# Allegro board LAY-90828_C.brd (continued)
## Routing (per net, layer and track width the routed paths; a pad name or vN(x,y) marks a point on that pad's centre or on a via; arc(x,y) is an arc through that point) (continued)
P1_7: length 53.4
  TOP w0.102: 59.36,32.33 U1.A2
  TOP w0.127: 59.36,32.33 58.61,33.08 58.61,34.1 56.32,36.39 R22.1 56.7,36.9 56.96,37.15 56.96,42.1 59.01,44.15 v1(59.01,46.18)
  BOTTOM w0.127: v1(59.01,46.18) 59.26,46.43 74.25,46.43 74.88,45.8 90.62,45.8 91.88,47.06 J9.9
P1_7/SAI1_RX_FS: length 24.9
  TOP w0.127: v1(58.24,46.18) 58.24,43.77 56.7,42.23 56.7,38.29 R22.2
  BOTTOM w0.127: J1.13 45.64,47.07 49.86,47.07 50.5,46.43 57.99,46.43 v1(58.24,46.18)
P1_8: length 56.2
  TOP w0.102: 58.86,32.33 U1.A1
  TOP w0.127: v1(87.45,42.5) 87.95,42.99 87.95,50.36 89.22,51.63 J9.12 ; 58.86,32.33 58.23,32.96 57.72,32.96 R54.2 56.96,34.74 55.56,36.14 55.56,38.42 56.2,39.06 56.2,42.48 56.85,43.13 v1(56.85,43.89)
  BOTTOM w0.127: v1(87.45,42.5) 86.95,43 74.22,43 73.46,43.77 65.48,43.77 65.36,43.64 57.48,43.64 57.23,43.89 v1(56.85,43.89)
P1_9: length 57.8
  TOP w0.102: 58.86,31.83 U1.B1
  TOP w0.127: J9.11 88.22,47.96 v1(88.22,42.5) ; 58.86,31.83 57.98,32.71 R53.2 56.96,33.09 56.83,33.21 54.82,33.21 54.69,33.34 54.69,37.93 55.94,39.18 55.94,42.61 56.34,43 v1(56.34,44.4)
  BOTTOM w0.127: v1(56.34,44.4) 57.1,44.4 57.61,43.89 65.23,43.89 65.36,44.02 73.58,44.02 74.35,43.26 87.45,43.26 v1(88.22,42.5)
P1_10/SMARTDMA_PIO6-CAMERA_D6: length 59.6
  TOP w0.102: 58.86,31.44 59.59,30.71 60.48,30.71 U1.C3
  TOP w0.127: v1(86.06,41.99) 85.66,42.39 85.66,50.23 86.8,51.38 J9.14 ; 58.86,31.44 58.1,32.2 54.93,32.2 54.43,32.69 54.43,38.06 55.69,39.31 55.69,43.24 v1(55.83,43.39)
  BOTTOM w0.127: v1(86.06,41.99) 85.55,42.5 73.87,42.5 73.1,43.26 65.74,43.26 65.61,43.13 56.09,43.13 v1(55.83,43.39)
P1_11/SMARTDMA_PIO7-CAMERA_D7: length 58.7
  TOP w0.102: U1.D3 60.18,30.5 59.41,30.5 58.86,31.06
  TOP w0.127: v1(86.69,42.5) 86.8,42.61 J9.13 ; v1(55.58,44.4) 55.32,44.15 55.32,42.75 55.43,42.64 55.43,39.44 54.18,38.18 54.18,32.56 54.8,31.94 57.97,31.94 58.86,31.06
  BOTTOM w0.127: v1(86.69,42.5) 86.44,42.75 74.09,42.75 73.33,43.51 65.61,43.51 65.48,43.39 56.59,43.39 v1(55.58,44.4)
P1_12/SMARTDMA_PIO8: length 40.6
  TOP w0.102: 58.86,30.67 59.25,30.29 59.9,30.29 U1.D2
  TOP w0.127: 58.86,30.67 57.85,31.69 54.67,31.69 53.93,32.44 53.93,38.43 54.94,39.45 v1(54.94,41.29) ; v1(67.33,41.04) 67.26,41.1 67.26,43.13 68.02,43.89 68.02,49.86 69.02,50.86 J9.28
  BOTTOM w0.127: v1(54.94,41.29) 55.13,41.1 56.85,41.1 57.23,40.72 63.71,40.72 63.83,40.85 67.13,40.85 v1(67.33,41.04)
P1_13/SMARTDMA_PIO9: length 39
  TOP w0.102: U1.D1 59.16,30 58.86,30.29
  TOP w0.127: 58.86,30.29 57.72,31.44 54.55,31.44 53.67,32.31 53.67,38.69 54.18,39.19 v1(54.18,41.23) ; J9.27 69.02,44.13 67.9,43 v1(67.9,41.48)
  BOTTOM w0.127: v1(67.9,41.48) 67.9,40.85 67.64,40.59 63.96,40.59 63.83,40.46 57.1,40.46 56.72,40.85 54.56,40.85 v1(54.18,41.23)
P1_14/SMARTDMA_PIO10: length 76.5
  TOP w0.102: U1.D4 60.89,29.7 59.07,29.7 58.86,29.91
  TOP w0.127: v1(54.69,44.91) 54.94,44.66 54.94,42.75 53.42,41.23 53.42,32.18 54.42,31.18 57.59,31.18 58.86,29.91
  BOTTOM w0.127: v1(54.69,44.91) 54.94,45.16 57.1,45.16 57.86,44.4 64.98,44.4 65.1,44.53 73.84,44.53 74.6,43.77 91.9,43.77 92.16,43.5 98.11,43.5 100.92,46.31 100.92,50.5 J9.2
P1_15/SMARTDMA_PIO11: length 74.2
  TOP w0.102: U1.E4 58.9,29.5 58.86,29.53
  TOP w0.127: v1(54.43,44.27) 54.43,42.75 53.16,41.48 53.16,32.06 54.29,30.93 57.47,30.93 58.86,29.53
  BOTTOM w0.127: v1(54.43,44.27) 54.82,44.27 55.45,44.91 56.97,44.91 57.74,44.15 65.1,44.15 65.23,44.27 73.71,44.27 74.47,43.51 91.77,43.51 92.04,43.25 98.37,43.25 102.04,46.93 J9.1
P1_16: length 93
  TOP w0.102: U1.F6 v2(62.19,28.52)
  TOP w0.127: R39.1 v1(64.21,39.7) 63.58,39.07 63.58,33.73 v1(63.96,33.35) ; v1(80.72,31.19) 80.72,32.72 76.15,37.29 76.15,37.92 76.79,38.56 v1(76.79,39.45)
  BOTTOM w0.102: v2(62.19,28.52) 62.19,29.17 62.29,29.28 62.29,30.42 63.05,31.18 63.05,32.33
  BOTTOM w0.127: 63.05,32.33 63.96,33.23 v1(63.96,33.35) ; J9.4 100.91,53.04 102.57,53.04 103.46,52.15 103.46,47.83 96.09,40.46 78.06,40.46 77.04,39.45 v1(76.79,39.45) 76.66,39.32 72.6,39.32 71.83,40.08 64.59,40.08 v1(64.21,39.7) ; v1(80.72,31.19) 80.72,30.43 83.6,27.56 83.6,20.06 84.14,19.53 J6.3
P1_16/FC5_I2C_SDA-ARD_D18: length 58.7
  TOP w0.127: v1(63.32,45.16) 63.32,45.04 64.21,44.15 R39.2 ; J2.18 16.73,51.63 17.86,50.5 17.86,48.21 18.49,47.58 19.89,47.58 21.67,45.8 23.83,45.8 24.46,45.16 R6.2 26.62,45.8 28.91,45.8 31.57,43.13 40.21,43.13 42.12,45.04 v1(42.12,45.29)
  BOTTOM w0.127: v1(63.32,45.16) 62.94,45.16 62.69,44.91 58.12,44.91 57.36,45.67 54.05,45.67 53.16,44.78 50.5,44.78 49.23,46.05 43.26,46.05 42.5,45.29 v1(42.12,45.29)
P1_17: length 122.7
  TOP w0.102: U1.F4 60.91,29.28 58.86,29.28
  TOP w0.127: 58.86,29.28 58.74,29.28 57.34,30.67 54.16,30.67 52.91,31.93 v1(52.91,43.51) 53.42,43.51 53.67,43.77 ; v1(97.36,44.27) 97.36,43.13 101.3,39.19 102.69,39.19 106.89,35 106.89,13.54 101.3,7.95 101.3,6.81 100.65,6.16 J7.1
  BOTTOM w0.127: v1(52.91,43.51) 52.91,44.15 54.18,45.42 57.23,45.42 57.99,44.66 64.85,44.66 64.98,44.78 73.97,44.78 74.73,44.02 92.03,44.02 92.28,43.77 96.85,43.77 v1(97.36,44.27) 97.49,44.15 98.25,44.15 99.5,45.4 J9.3
P1_17/FC5_I2C_SCL-ARD_D19: length 48.1
  TOP w0.127: v1(53.04,45.29) 53.16,45.29 R40.2 ; v1(42.5,46.05) 42.75,45.8 42.75,45.16 40.34,42.75 31.45,42.75 29.8,44.4 26.62,44.4 R7.2 25.1,43.77 23.45,45.42 21.54,45.42 19.76,47.2 16.33,47.2 15.19,48.34 15.19,50.62 14.19,51.63 J2.20
  BOTTOM w0.127: v1(53.04,45.29) 52.91,45.16 50.5,45.16 49.35,46.31 42.75,46.31 v1(42.5,46.05)
P1_18/SMARTDMA_PIO14-CAMERA_PDOWN: length 69.8
  TOP w0.102: U1.G4 v2(61.19,28.01)
  TOP w0.127: v1(61.04,51.77) 60.66,51.39 60.66,48.34 59.64,47.32 58.63,47.32 57.36,46.05 57.36,43.26 56.45,42.35 56.45,38.93 55.82,38.29 55.82,36.39 57.85,34.36 v1(57.85,33.61)
  BOTTOM w0.102: 58.86,28.91 61.01,28.91 61.19,28.73 v2(61.19,28.01)
  BOTTOM w0.127: v1(57.85,33.61) 56.85,32.61 56.85,29.29 57.23,28.91 58.86,28.91 ; v1(61.04,51.77) 61.29,52.02 62.05,52.02 63.71,53.67 94.92,53.67 J9.6
P1_19/SMARTDMA_PIO15-CAMERA_RST: length 53.1
  TOP w0.102: U1.G5 v2(61.69,29.02)
  TOP w0.127: v1(64.47,45.16) 64.47,45.04 64.98,44.53 64.98,39.19 64.21,38.43 64.21,34.31 v1(64.02,34.12)
  BOTTOM w0.102: 62.8,32.33 62.8,31.31 62.04,30.55 62.04,29.38 v2(61.69,29.02)
  BOTTOM w0.127: 62.8,32.33 62.8,32.83 64.02,34.06 v1(64.02,34.12) ; v1(64.47,45.16) 64.59,45.04 74.09,45.04 74.85,44.27 91.65,44.27 93.3,45.93 93.8,45.93 J9.5
P1_30/XTAL48M: length 7.3
  TOP w0.102: 58.97,29.01 59.68,29.01 U1.F1
  TOP w0.127: Y3.1 53.26,29.3 53.4,29.15 54.8,29.15 55.06,29.41 C96.1 56.06,29.41 56.2,29.27 R170.1 56.73,29.25 57.12,29.25 57.36,29.01 58.97,29.01
P1_31/EXTAL48M: length 6.2
  TOP w0.102: 58.86,28.75 58.97,28.75 58.99,28.73 59.2,28.73 59.2,28.73 59.92,28.73 U1.F2
  TOP w0.127: 58.86,28.75 57.45,28.75 57.2,28.5 56.73,28.5 R170.2 56.19,28.52 56.08,28.64 C97.1 55.05,28.64 54.89,28.48 Y3.3
P2_0: length 43.8
  TOP w0.102: 58.86,28.2 58.93,28.27 59.92,28.27 U1.H2
  TOP w0.127: J1.6 52.76,52.66 47.96,52.66 47.32,52.02 47.32,46.69 47.83,46.18 47.83,34.11 v1(47.2,33.48) ; v1(52.15,30.09) 51.88,29.82 51.88,28.64 53.15,27.37 56.83,27.37 57.59,28.14 58.8,28.14 58.86,28.2
  BOTTOM w0.127: v1(52.15,30.09) SJ3.1 50.5,30.09 50.37,30.22 50.37,30.94 49.1,32.21 48.47,32.21 v1(47.2,33.48)
P2_1/GPIO: length 46.6
  TOP w0.102: U1.H1 58.98,28 58.86,27.88
  TOP w0.127: 58.86,27.88 58.86,27.88 57.72,27.88 56.96,27.12 53.02,27.12 51.62,28.52 51.62,31.18 52.15,31.71 52.15,39.19 51.64,39.7 51.64,43 51.89,43.26 51.89,45.54 54.05,47.7 54.56,47.7 54.94,48.08 54.94,49.61 55.58,50.24 59.39,50.24 60.4,51.26 60.4,52.66 60.78,53.04 65.08,53.04 J9.30
P2_2/CLKOUT-SMARTDMA_CAMERA_CLKIN: length 71.8
  TOP w0.102: 58.86,27.63 58.99,27.63 59.09,27.73 60.42,27.73 U1.H3
  TOP w0.127: 58.86,27.63 57.85,27.63 57.09,26.86 52.89,26.86 51.37,28.39 51.37,31.31 51.89,31.83 51.89,39.07 51.39,39.58 v1(51.39,44.27) ; J9.16 85.3,50.6 v1(85.3,41.99)
  BOTTOM w0.127: v1(85.3,41.99) 85.04,42.24 73.74,42.24 72.98,43 65.86,43 65.74,42.88 52.78,42.88 v1(51.39,44.27)
P2_3/FXIO_D11: length 99.7
  TOP w0.102: 58.86,27.37 59.12,27.37 59.24,27.5 U1.J3
  TOP w0.127: 58.86,27.37 57.97,27.37 57.21,26.61 54.93,26.61 v1(53.78,25.47)
  BOTTOM w0.127: J8.20 111.57,19.88 113.47,19.88 114.74,18.61 114.74,9.84 113.23,8.33 98.6,8.33 98.1,8.84 94.82,8.84 94.31,8.33 87.71,8.33 86.69,9.35 83.39,9.35 80.47,6.43 64.34,6.43 60.66,10.11 60.66,15.06 59.9,15.83 59.9,18.97 59.61,19.26 58.34,19.26 57.47,20.13 57.47,22.55 55.94,24.07 55.18,24.07 v1(53.78,25.47)
P2_4/FXIO_D12: length 93.5
  TOP w0.102: 58.86,27.12 59.24,27.12 59.4,27.27 60.3,27.27 60.45,27.12 60.57,27.12 U1.K3
  TOP w0.127: 58.86,27.12 58.1,27.12 57.34,26.36 55.31,26.36 54.55,25.59 v1(54.55,25.47)
  BOTTOM w0.127: v1(54.55,25.47) 55.69,24.32 56.07,24.32 57.72,22.67 57.72,20.26 58.47,19.51 59.74,19.51 60.15,19.1 60.15,15.95 60.91,15.19 60.91,10.37 64.59,6.68 80.22,6.68 83.26,9.73 86.82,9.73 87.96,8.59 94.19,8.59 94.69,9.1 98.22,9.1 98.73,8.59 113.1,8.59 114.48,9.97 114.48,17.85 113.73,18.61 J8.21
P2_5/FXIO_D13: length 91.6
  TOP w0.102: U1.K1 59.6,26.91 58.9,26.91 58.86,26.86
  TOP w0.127: 58.86,26.86 58.23,26.86 57.47,26.1 55.82,26.1 55.31,25.59 v1(55.31,25.47)
  BOTTOM w0.127: v1(55.31,25.47) 57.97,22.8 57.97,20.39 58.6,19.76 59.87,19.76 60.4,19.23 60.4,16.08 61.17,15.32 61.17,10.62 64.72,7.06 80.22,7.06 83.26,10.11 86.82,10.11 88.09,8.84 94.06,8.84 94.57,9.35 98.35,9.35 98.86,8.84 112.98,8.84 114.23,10.1 114.23,16.46 113.35,17.34 111.57,17.34 J8.22
P2_6/FXIO_D14: length 85.6
  TOP w0.102: U1.K2 59.89,26.7 59.08,26.7 58.99,26.61 58.86,26.61
  TOP w0.127: v1(56.07,25.47) 56.32,25.21 57.09,25.21 58.48,26.61 58.86,26.61
  BOTTOM w0.127: v1(56.07,25.47) 56.07,25.09 58.23,22.93 58.23,20.51 58.73,20.02 60,20.02 60.66,19.36 60.66,16.21 61.42,15.45 61.42,10.87 64.98,7.32 79.96,7.32 83.14,10.49 86.95,10.49 88.34,9.1 93.93,9.1 94.44,9.6 98.48,9.6 98.98,9.1 112.85,9.1 113.98,10.22 113.98,14.93 J8.23
P2_7: length 68.7
  TOP w0.102: 58.86,26.36 59.12,26.36 59.26,26.5 U1.L2
  TOP w0.127: v1(46.56,34.62) 47.2,35.26 47.2,45.8 44.91,48.08 44.91,50.12 46.16,51.37 J1.12 ; v1(52.28,26.62) 52.28,26.49 52.91,25.86 52.91,25.58 53.53,24.96 57.21,24.96 58.61,26.36 58.86,26.36
  BOTTOM w0.127: J3.13 38.54,7.43 49.09,17.99 52.91,17.99 53.42,18.49 53.42,23.95 52.28,25.1 v1(52.28,26.62) 52.28,26.75 50.12,28.91 50.12,30.81 48.97,31.96 48.08,31.96 46.56,33.48 v1(46.56,34.62)
P2_8/SAI1_TXD0: length 88.8
  TOP w0.102: 58.86,26.1 59.24,26.1 59.41,26.27 59.92,26.27 U1.M2
  TOP w0.127: 58.86,26.1 58.74,26.1 57.34,24.71 53.15,24.71 51.75,26.1 51.75,27.63 51.12,28.26 51.12,31.43 51.64,31.96 51.64,38.94 50.88,39.7 50.88,44.91 53.78,47.81 J1.5 ; R109.1 95.31,35.51 95.31,36.01 95.57,36.26 95.57,44.93 94.69,45.8 91.14,45.8 v1(89.87,47.07)
  BOTTOM w0.127: v1(89.87,47.07) 89.23,47.7 54.79,47.7 53.78,48.71 J1.5
P2_9/SAI1_RXD0: length 98.2
  TOP w0.102: 58.86,25.85 59.37,25.85 59.52,26 U1.M1
  TOP w0.127: R107.1 95.35,32.59 94.82,32.59 93.15,34.26 93.15,39.85 91.26,41.73 v1(91.26,45.04) ; v1(51.26,45.93) 50.62,45.29 50.62,39.58 51.39,38.81 51.39,32.08 50.86,31.56 50.86,28.13 51.5,27.5 51.5,25.98 53.02,24.45 57.47,24.45 58.86,25.85
  BOTTOM w0.127: v1(91.26,45.04) 91.01,45.29 74.63,45.29 73.99,45.93 61.55,45.93 61.04,45.42 58.37,45.42 57.61,46.18 51.51,46.18 v1(51.26,45.93) 50.5,45.93 49.61,46.81 43.36,46.81 J1.15
P2_10/SMARTDMA_PIO31: length 59.6
  TOP w0.102: 58.86,25.47 58.99,25.59 59.5,25.59 59.63,25.72 60.41,25.72 U1.M3
  TOP w0.127: J9.24 74.1,51.25 72.83,49.98 72.83,46.07 73.61,45.29 73.61,41.99 v1(70.44,38.81) ; 58.86,25.47 57.59,24.2 52.89,24.2 51.24,25.85 51.24,27.37 50.61,28.01 50.61,31.69 51.13,32.21 51.13,38.43 v1(50.88,38.69)
  BOTTOM w0.127: v1(70.44,38.81) 70.18,39.07 65.61,39.07 64.59,38.05 53.42,38.05 53.04,38.43 51.13,38.43 v1(50.88,38.69)
P2_11/SMARTDMA_PIO30: length 61
  TOP w0.102: U1.N4 59.78,25.5 59.63,25.34 59.12,25.34 58.86,25.09
  TOP w0.127: 58.86,25.09 57.72,23.94 52.77,23.94 50.99,25.72 50.99,27.25 50.35,27.88 50.35,31.81 50.88,32.34 50.88,37.54 50.24,38.18 50.24,39.19 50.12,39.32 v1(50.12,42.5) ; J9.26 71.56,51.12 70.29,49.85 70.29,44.77 68.4,42.88 68.4,40.72 v1(68.28,40.59)
  BOTTOM w0.127: v1(50.12,42.5) 50.12,42.12 50.75,41.48 53.29,41.48 54.18,40.59 56.59,40.59 56.97,40.21 63.96,40.21 64.09,40.34 68.02,40.34 v1(68.28,40.59)
P3_0/FXIO_D8: length 55.8
  TOP w0.102: 68.52,31.69 67.82,31 U1.B17
  TOP w0.127: v1(71.69,33.34) 71.44,33.09 69.91,33.09 68.52,31.69
  BOTTOM w0.127: v1(71.69,33.34) 71.69,33.6 71.94,33.85 92.52,33.85 94.42,35.75 104.96,35.75 106.36,34.36 106.36,28.26 109.54,25.09 111.44,25.09 J8.17
P3_1/FXIO_D9: length 54.2
  TOP w0.102: 68.52,31.31 67.88,30.67 66.86,30.67 U1.C15
  TOP w0.127: 68.52,31.31 70.04,32.83 71.94,32.83 v1(72.45,33.34)
  BOTTOM w0.127: v1(72.45,33.34) 72.71,33.6 92.65,33.6 94.55,35.5 104.71,35.5 106.11,34.1 106.11,27.88 J8.18
P3_2/FXIO_D10: length 58.6
  TOP w0.102: 68.52,30.93 68.01,30.42 67.12,30.42 66.7,30 U1.D15
  TOP w0.127: v1(70.31,32.21) 69.8,32.21 68.52,30.93
  BOTTOM w0.127: J8.19 111.57,22.42 109.79,22.42 105.85,26.36 105.85,33.98 104.58,35.25 94.68,35.25 92.77,33.34 73.09,33.34 72.45,32.71 70.81,32.71 v1(70.31,32.21)
P3_6/SAI1_MCLK: length 84.8
  TOP w0.102: 68.52,30.55 67.97,30 U1.D17
  TOP w0.127: v1(75.39,47.07) 75.38,47.06 75.38,46.55 74.25,45.42 74.25,34.37 72.45,32.58 72.45,31.94 72.07,31.56 69.53,31.56 68.52,30.55 ; v1(89.11,46.69) 89.11,45.93 90.88,44.15 90.88,41.61 92.9,39.59 92.9,36.89 91.39,35.38 91.39,33.86 93.42,31.83 93.42,30.02 95.31,28.13 R103.2
  BOTTOM w0.127: J1.7 51.24,47.72 51.51,47.45 75.01,47.45 v1(75.39,47.07) 75.64,47.32 88.47,47.32 v1(89.11,46.69)
P3_7/FXIO_D15: length 62.3
  TOP w0.102: 68.52,30.17 68.06,29.71 66.43,29.71 66.19,29.95 U1.D14
  TOP w0.127: 68.52,30.17 69.66,31.31 72.2,31.31 72.96,32.07 v1(72.96,32.33)
  BOTTOM w0.127: J8.24 105.6,20.77 105.6,33.85 104.46,34.99 94.8,34.99 92.9,33.09 73.34,33.09 72.96,32.71 v1(72.96,32.33)
P3_8/FXIO_D16: length 68.2
  TOP w0.102: 68.52,29.79 68.23,29.5 U1.E14
  TOP w0.127: 68.52,29.79 69.79,31.06 72.58,31.06 v1(72.96,31.44)
  BOTTOM w0.127: J8.25 111.57,12.26 109.79,12.26 105.09,16.96 105.09,33.6 104.2,34.48 95.06,34.48 93.15,32.58 74.23,32.58 73.47,31.82 73.34,31.82 v1(72.96,31.44)
P3_9/FXIO_D17: length 64.4
  TOP w0.102: U1.F15 66.98,29.29 68.4,29.29 68.52,29.4
  TOP w0.127: 68.52,29.4 69.91,30.8 72.96,30.8 73.47,31.31 73.47,32.45 v1(73.6,32.58)
  BOTTOM w0.127: J8.26 105.35,18.48 105.35,33.72 104.33,34.74 94.93,34.74 93.03,32.83 73.85,32.83 v1(73.6,32.58)
P3_10/FXIO_D18: length 68.9
  TOP w0.102: 68.52,29.02 67.71,29.02 U1.F17
  TOP w0.127: 68.52,29.02 68.54,29.02 70.06,30.55 73.09,30.55 74.36,31.82 v1(74.48,31.82)
  BOTTOM w0.102: 101.09,33.34 98.11,33.34 97.66,33.79
  BOTTOM w0.127: 101.09,33.34 101.54,33.34 102.17,33.98 103.82,33.98 104.58,33.21 104.58,14.93 109.66,9.85 111.7,9.85 J8.27 ; 97.66,33.79 97.47,33.98 95.31,33.98 93.41,32.07 74.74,32.07 v1(74.48,31.82)
P3_11/FXIO_D19: length 66.3
  TOP w0.102: 68.52,28.75 67.86,28.75 67.81,28.7 67.49,28.7 U1.F16
  TOP w0.127: 68.52,28.75 68.63,28.75 68.64,28.77 68.64,28.77 70.17,30.29 73.47,30.29 v1(73.72,30.55)
  BOTTOM w0.102: 97.66,34.17 98.23,33.6 101.09,33.6
  BOTTOM w0.127: 101.09,33.6 101.41,33.6 102.04,34.23 104.08,34.23 104.84,33.47 104.84,16.45 J8.28 ; v1(73.72,30.55) 73.72,31.69 74.36,32.33 93.28,32.33 95.19,34.23 97.6,34.23 97.66,34.17
P3_12: length 10.8
  TOP w0.102: 68.52,28.5 U1.G16
  TOP w0.127: 68.52,28.5 68.75,28.5 70.29,30.04 73.85,30.04 74.36,30.55 v1(74.36,31.06) 74.87,31.56 R35.1 R37.1
P3_12/FC6_QSPI_D3: length 19.4
  TOP w0.127: R186.2 92.38,25.08 92.15,24.85 U12.7 87.97,24.83 83.14,29.67 81.61,29.67 80.98,30.3 80.47,30.3 v1(80.22,30.56) ; R35.2 76.42,31.56 v1(77.17,30.81)
  BOTTOM w0.127: v1(80.22,30.56) 77.42,30.56 v1(77.17,30.81)
P3_12/PWM1_A0: length 107.1
  TOP w0.127: v1(77.29,31.57) 77.29,31.67 R37.2 76.39,34.13 74.5,36.02 74.5,45.29 76.03,46.81 v1(76.15,46.81) ; v1(49.47,7.69) 49.72,7.94 56.7,7.94 63.18,14.42 63.18,15.43 64.84,17.09 71.69,17.09 72.2,16.58 76.39,16.58 78.93,19.12 78.93,19.5 v1(79.95,20.51)
  BOTTOM w0.127: v1(79.95,20.51) 79.95,25.75 76.53,29.16 76.53,31.07 77.04,31.57 v1(77.29,31.57) ; v1(49.47,7.69) 48.83,7.05 42.23,7.05 J3.15 ; J1.8 51.24,51.62 49.99,50.37 49.99,48.34 51.13,47.2 74.63,47.2 75.26,46.56 75.9,46.56 v1(76.15,46.81)
P3_13: length 9.3
  TOP w0.102: 68.52,28.25 68.28,28.25 68.23,28.29 67.48,28.29 U1.H16
  TOP w0.127: 68.52,28.25 68.88,28.25 69.53,28.9 70.55,28.9 71.31,29.66 74.1,29.66 v1(74.36,29.91) 74.99,30.55 R36.1
P3_13/FC6_QSPI_D2: length 16.8
  TOP w0.127: U12.3 81.49,23.58 R188.2 v1(81.47,24.32) ; R36.2 76.54,30.55 v1(77.04,30.05)
  BOTTOM w0.127: v1(81.47,24.32) 81.47,24.96 80.89,25.54 80.89,25.71 81.16,25.98 81.16,26.16 80.98,26.34 80.8,26.34 80.53,26.07 80.35,26.07 80.18,26.25 80.18,26.43 80.5,26.76 80.5,26.94 80.32,27.12 80.14,27.12 79.82,26.79 79.64,26.79 79.46,26.97 79.46,27.15 79.79,27.48 79.79,27.66 79.61,27.84 79.43,27.84 79.1,27.51 78.92,27.51 78.74,27.69 78.74,27.87 79.13,28.26 79.13,28.44 78.95,28.62 78.77,28.62 78.38,28.23 78.2,28.23 78.02,28.41 78.02,28.59 78.28,28.85 78.28,29.03 78.11,29.21 77.93,29.21 77.66,28.95 77.48,28.95 77.17,29.26 77.17,29.92 v1(77.04,30.05)
P3_14: length 155.8
  TOP w0.102: U1.H17 67.7,27.99 68.52,27.99
  TOP w0.127: J2.4 37.16,54.31 81.1,54.31 83.14,52.28 83.14,42.62 83.9,41.86 v1(83.9,41.48) ; v1(75.01,40.21) 74.75,39.96 74.75,36.27 77.8,33.23 77.8,30.05 77.29,29.54 76.66,29.54 76.28,29.92 75.52,29.92 v1(75.26,29.67) 75,29.67 74.74,29.4 71.44,29.4 70.67,28.64 69.66,28.64 69.02,28.01 69,28.01 68.99,27.99 68.52,27.99 ; v1(47.69,7.94) 48.2,8.45 56.32,8.45 62.67,14.8 62.67,15.68 64.58,17.59 71.94,17.59 72.45,17.09 76.14,17.09 77.66,18.61 v1(77.66,19.75)
  BOTTOM w0.127: v1(77.66,19.75) 77.04,20.37 77.04,27.38 75.26,29.16 v1(75.26,29.67) ; v1(47.69,7.94) 47.31,7.56 40.7,7.56 39.83,6.69 39.83,5.14 39.34,4.65 37.26,4.65 J3.11 ; v1(75.01,40.21) 76.02,40.21 76.53,40.72 83.14,40.72 v1(83.9,41.48)
P3_15: length 106.5
  TOP w0.102: 68.52,27.71 66.98,27.71 U1.H15
  TOP w0.127: 68.52,27.71 69.1,27.71 69.79,28.39 70.8,28.39 71.56,29.15 75.76,29.15 v1(76.02,29.42) 76.28,29.16 77.29,29.16 78.06,29.92 78.06,33.61 75.01,36.65 75.01,39.07 75.52,39.58 75.52,40.72 v1(75.26,40.97) ; v1(78.42,19.75) 78.42,18.99 76.26,16.83 72.33,16.83 71.82,17.34 64.71,17.34 62.93,15.56 62.93,14.67 56.45,8.2 48.96,8.2 v1(48.58,7.81)
  BOTTOM w0.127: SJ1.3 61.42,41.86 61.55,41.99 62.56,41.99 62.94,41.61 65.86,41.61 66.5,42.24 68.15,42.24 69.8,40.59 72.09,40.59 72.85,39.83 73.74,39.83 74.88,40.97 v1(75.26,40.97) ; v1(76.02,29.42) 76.02,29.03 77.42,27.64 77.42,23.19 78.18,22.43 78.18,19.99 v1(78.42,19.75) ; J3.9 34.98,4.4 39.44,4.4 40.08,5.04 40.08,6.56 40.83,7.31 48.07,7.31 v1(48.58,7.81)
P3_16: length 150.9
  TOP w0.102: U1.J15 68.01,27.5 68.05,27.45 68.52,27.45
  TOP w0.127: 68.52,27.45 69.23,27.45 69.91,28.13 70.93,28.13 71.69,28.9 77.41,28.9 78.31,29.8 78.31,34.11 75.64,36.78 75.64,38.18 76.02,38.56 76.02,44.66 77.04,45.67 77.04,47.45 v1(77.8,48.21) ; R106.1 95.82,35.89 95.82,45.05 94.57,46.31 91.39,46.31 v1(90.76,46.94) ; v1(52.91,31.19) 52.66,31.45 52.66,39.58 52.49,39.74 52.49,39.96 v1(52.43,40.02) 52.43,45.32 54.31,47.2 57.86,47.2 58.86,48.2 J1.1
  BOTTOM w0.127: J1.1 60,47.96 77.55,47.96 v1(77.8,48.21) 78.06,47.96 89.74,47.96 v1(90.76,46.94) ; J3.7 32.08,7.06 36.53,7.06 37.29,6.3 37.29,5.29 37.67,4.9 39.07,4.9 39.58,5.41 39.58,7.95 49.35,17.73 53.04,17.73 53.67,18.37 53.67,24.21 52.91,24.97 v1(52.91,31.19) ; v1(52.43,40.02) 53.51,38.94 SJ2.3
P3_17: length 160.2
  TOP w0.102: 68.52,27.2 67.93,27.2 67.83,27.29 66.98,27.29 U1.K15
  TOP w0.127: v1(78.95,31.45) 78.95,30.05 77.54,28.64 71.82,28.64 71.06,27.88 70.04,27.88 69.4,27.25 69.38,27.25 69.34,27.2 68.52,27.2 ; J1.11 46.16,47.31 47.45,46.03 47.45,34.5 v1(47.2,34.24) 46.43,33.48 46.43,31.96 45.53,31.06 45.53,24.32 43.5,22.29 43.5,19.75 v1(42.99,19.24) ; R108.1 95.9,33.93 v1(95.06,33.09) 94.8,33.34 94.8,35.88 95.31,36.39 95.31,44.8 94.57,45.54 90.5,45.54 89.87,46.18 v1(89.87,46.31)
  BOTTOM w0.127: v1(89.87,46.31) 89.61,46.05 75.01,46.05 74.37,46.69 50.62,46.69 49.99,47.32 46.94,47.32 46.16,48.1 J1.11 J1.14 ; J3.5 31.05,8.58 31.05,13.15 36.26,18.36 37.4,18.36 38.29,19.24 v1(42.99,19.24) ; v1(95.06,33.09) 93.67,31.7 79.2,31.7 v1(78.95,31.45) ; v1(47.2,34.24) 47.45,34.24 49.23,32.46 50.59,32.46 SJ3.3
P3_18/SAI1_RX_BCLK: length 62.5
  TOP w0.102: U1.K16 67.48,26.71 67.98,26.71 68.13,26.86 68.52,26.86
  TOP w0.127: 68.52,26.86 69.87,26.86 69.87,26.86 70.42,26.86 71.94,28.39 77.66,28.39 79.45,30.18 79.45,33.48 75.9,37.04 75.9,38.05 76.28,38.43 76.28,44.4 77.55,45.67 v1(77.55,46.56)
  BOTTOM w0.127: v1(77.55,46.56) 77.29,46.31 75.14,46.31 74.5,46.94 50.85,46.94 J1.9
P3_20: length 15.3
  TOP w0.102: U1.M17 67.78,26.09 68.41,26.09 68.42,26.1 68.52,26.1
  TOP w0.127: 68.52,26.1 70.19,26.1 70.19,26.1 70.8,26.1 72.33,27.63 77.69,27.63 78.18,27.13 80.46,27.13 v1(80.96,27.63) 81.34,27.63 R32.1
P3_20/FC6_QSPI_D0: length 13.5
  TOP w0.127: R32.2 83.76,28.01 86.04,25.72 86.04,25.04 85.9,24.9 85.9,24.72 86.08,24.54 86.26,24.54 86.53,24.8 86.7,24.8 86.88,24.62 86.88,24.44 86.62,24.18 86.62,24 86.8,23.82 86.98,23.82 87.24,24.09 87.42,24.09 87.6,23.91 87.6,23.73 87.34,23.46 87.34,23.28 87.52,23.1 87.7,23.1 87.9,23.3 88.08,23.3 88.26,23.12 88.26,22.74 88.7,22.3 v1(89.09,22.3) 89.46,22.3 U12.5
P3_21: length 18.3
  TOP w0.102: 68.52,26.61 68.24,26.61 68.13,26.5 U1.L16
  TOP w0.127: 68.52,26.61 69.98,26.61 69.98,26.61 70.55,26.61 72.07,28.13 78.17,28.13 79.06,29.02 79.31,29.02 v1(79.44,29.15) 79.44,29.66 79.56,29.79 79.82,29.79 79.95,29.66 79.95,29.15 80.07,29.02 80.33,29.02 80.45,29.15 80.45,29.79 80.58,29.91 80.83,29.91 80.96,29.79 80.96,29.15 81.09,29.02 R33.1
P3_21/FC6_QSPI_SCK: length 10.3
  TOP w0.127: R33.2 83.25,29.02 88.7,23.58 v1(89.08,23.57) U12.6
P3_22: length 12.5
  TOP w0.102: 68.52,26.36 68.28,26.36 68.22,26.3 67.49,26.3 U1.M16
  TOP w0.127: 68.52,26.36 70.08,26.36 70.08,26.36 70.67,26.36 72.2,27.88 R34.1
P3_22/FC6_QSPI_D1: length 15.6
  TOP w0.127: R34.2 v1(80.58,28.52) ; U12.2 82.36,24.83 v1(82.1,24.58)
  BOTTOM w0.127: v1(80.58,28.52) 80.86,28.52 81.88,27.5 83.12,27.5 83.25,27.37 83.25,27.12 83.12,26.99 81.34,26.99 81.22,26.86 81.22,26.61 81.34,26.48 82.99,26.48 83.12,26.36 83.12,26.1 82.99,25.98 81.72,25.98 81.6,25.85 81.6,25.59 81.72,25.47 82.99,25.47 83.12,25.34 83.12,25.09 82.99,24.96 82.23,24.96 82.1,24.83 v1(82.1,24.58)
P3_23: length 13.4
  TOP w0.102: 68.52,25.85 68.01,25.85 67.87,25.71 66.98,25.71 U1.M15
  TOP w0.127: R31.1 78.32,26.61 77.56,27.37 72.45,27.37 70.93,25.85 70.29,25.85 70.29,25.85 68.52,25.85
P3_23/FC6_QSPI_CS0: length 3.8
  TOP w0.127: R31.2 80.96,26.61 R187.2 U12.1
P4_0: length 220.8
  TOP w0.102: U1.P1 59.16,25 58.86,24.71
  TOP w0.127: v1(106.25,37.04) 107.39,35.89 107.39,13.03 102.19,7.83 102.19,4.78 99.14,1.73 91.39,1.73 90.74,2.38 J7.8 ; v1(57.36,52.91) 58.5,54.05 77.8,54.05 79.18,52.67 J9.20 80.34,50.47 80.34,43.64 83.01,40.97 89.71,40.97 J5.6 91.76,38.42 91.01,37.67 89.61,37.67 89.11,37.16 89.11,35.75 v1(89.85,35) R49.1 ; 58.86,24.71 57.85,23.69 52.64,23.69 50.74,25.59 50.74,27.12 50.1,27.75 50.1,28.77 R44.2 49.21,30.03 v1(49.55,30.37) 49.55,30.5 49.35,30.69 49.35,31.57 50.62,32.84 50.62,37.42 49.99,38.05 49.99,39.07 49.61,39.45 49.61,45.04 51.89,47.32 52.28,47.32 v1(52.91,47.96) ; v1(30.54,15.05) 29.4,16.2 19.11,16.2 18.86,16.45 R210.2 ; v1(91.96,34.81) 91.96,33.67 94.52,31.11 R105.1
  BOTTOM w0.127: v1(89.85,35) 90.04,34.81 v1(91.96,34.81) 92.34,34.81 94.06,36.53 105.74,36.53 v1(106.25,37.04) 107.52,38.31 107.52,39.83 109.16,41.47 J8.4 ; v1(52.91,47.96) 52.66,48.21 52.66,49.99 53.16,50.5 56.97,50.5 57.48,51.01 57.48,52.78 v1(57.36,52.91) ; v1(49.55,30.37) 49.55,30.5 49.1,30.94 46.17,30.94 45.53,30.29 40.32,30.29 37.78,27.75 37.78,21.02 36.64,19.88 36.13,19.88 31.3,15.05 v1(30.54,15.05)
P4_0/FC2_I2C_SDA-ACCL: length 2.9
  TOP w0.127: R49.2 89.85,32.33 88.98,31.46 U10.4
P4_1: length 220.2
  TOP w0.102: U1.P2 59.77,24.58 59.12,24.58 58.86,24.32
  TOP w0.127: J7.6 93.28,2.51 93.68,2.11 99.01,2.11 101.83,4.93 101.83,7.97 107.14,13.29 107.14,35.38 105.62,36.91 v1(105.62,37.54) ; v1(92.41,35.51) 92.41,34.62 94.9,32.13 R104.1 ; R211.2 18.48,17.34 19.37,16.45 29.91,16.45 v1(30.54,15.82) ; 58.86,24.32 57.97,23.44 52.51,23.44 50.48,25.47 50.48,26.99 49.85,27.63 49.85,28.54 49.62,28.77 R43.2 49.21,28.39 49.08,28.26 47.94,28.26 47.69,28.52 47.69,30.17 48.85,31.33 v1(48.85,31.45) 50.37,32.97 50.37,37.29 49.74,37.92 49.74,38.94 49.35,39.32 49.35,45.29 v1(52.02,47.96) ; R50.1 88.84,34.99 v1(88.85,35) 88.72,35.13 88.72,37.42 89.22,37.91 J5.5 87.43,40.72 82.88,40.72 79.18,44.42 J9.19 79.18,50.13 78.18,51.13 78.18,52.91 77.29,53.8 59.01,53.8 v1(58.12,52.91)
  BOTTOM w0.127: v1(58.12,52.91) 57.61,53.42 53.29,53.42 52.4,52.53 52.4,48.21 52.15,47.96 v1(52.02,47.96) ; v1(48.85,31.45) 46.17,31.45 45.27,30.55 40.19,30.55 37.4,27.75 37.4,21.15 36.51,20.26 34.73,20.26 30.54,16.07 v1(30.54,15.82) ; J8.3 111.57,42.74 109.54,42.74 107.27,40.46 107.27,39.19 v1(105.62,37.54) 104.85,36.78 93.93,36.78 92.66,35.51 v1(92.41,35.51) 89.36,35.51 v1(88.85,35)
P4_1/FC2_I2C_SCL-ACCL: length 1.9
  TOP w0.127: R50.2 88.84,31.99 88.71,31.86 U10.5
P4_2: length 96.1
  TOP w0.102: 58.86,23.94 58.92,24 U1.T1
  TOP w0.127: v1(75.52,38.81) 75.77,39.07 75.77,44.91 76.79,45.93 76.79,47.2 75.64,48.34 75.64,52.53 74.88,53.29 60.66,53.29 60.15,52.78 60.15,51.39 59.26,50.5 57.99,50.5 56.86,51.63 J1.4 54.94,50.24 50.75,50.24 50.12,49.61 50.12,48.34 49.1,47.32 49.1,39.19 49.48,38.81 49.48,37.8 50.12,37.16 50.12,34.24 49.35,33.48 49.35,33.1 48.07,31.81 48.07,31.31 47.18,30.42 47.18,27.88 47.81,27.25 48.96,27.25 49.21,27.5 R55.2 50.23,26.74 50.23,25.34 52.39,23.18 58.11,23.18 58.86,23.94
  BOTTOM w0.127: v1(75.52,38.81) 76.79,38.81 78.18,40.21 85.4,40.21 J5.4
P4_3: length 89
  TOP w0.102: U1.U1 58.86,23.5
  TOP w0.127: 58.86,23.5 58.81,23.5 58.23,22.93 52.26,22.93 49.97,25.21 49.97,25.98 R56.2 49.21,26.36 49.08,26.23 47.56,26.23 46.67,27.12 46.67,30.67 47.56,31.56 47.56,32.07 48.85,33.35 48.85,34.37 49.86,35.38 49.86,37.04 49.23,37.67 49.23,38.69 48.85,39.07 48.85,47.45 49.86,48.47 49.86,49.74 50.62,50.5 54.56,50.5 55.2,51.13 55.2,52.66 55.58,53.04 56.47,53.04 57.87,51.63 J1.2 58.86,51.88 60.53,53.55 76.41,53.55 77.8,52.15 77.8,48.97 78.44,48.34 78.44,44.78 84.14,39.08 J5.3
P4_4/SMARTDMA_PIO28: length 29.5
  TOP w0.102: U1.M6 v2(62.19,26.48)
  TOP w0.127: v1(69.8,36.02) 69.8,38.94 73.1,42.24 73.1,45.16 71.56,46.7 J9.25
  BOTTOM w0.102: 65.98,32.33 64.72,31.07 64.72,29.43 63.05,27.76 63.05,26.85 62.68,26.48 v2(62.19,26.48)
  BOTTOM w0.127: 65.98,32.33 66.75,33.1 68.4,33.1 69.8,34.5 v1(69.8,36.02)
P4_5/SMARTDMA_PIO29: length 29.8
  TOP w0.102: U1.M8 v2(63.19,26.47)
  TOP w0.127: v1(73.48,36.02) 73.99,36.53 73.99,48.98 J9.23
  BOTTOM w0.102: 66.49,32.33 64.98,30.81 64.98,29.29 63.33,27.65 63.33,27.65 63.31,27.62 63.31,26.61 63.19,26.49 v2(63.19,26.47)
  BOTTOM w0.127: v1(73.48,36.02) 73.23,36.27 72.09,36.27 68.66,32.84 67.01,32.84 66.49,32.33
P4_6: length 126.1
  TOP w0.102: U1.N7 v2(62.2,25.5)
  TOP w0.127: J8.6 110.58,38.93 111.84,37.67 114.25,37.67 115.39,36.53 115.39,13.79 113.74,12.14 108.03,12.14 107.01,11.13 v1(106.5,11.13) ; v1(58.24,13.92) 58.37,13.79 59.38,13.79 61.92,16.33 62.56,16.33 64.47,18.24 v1(64.47,18.62)
  BOTTOM w0.102: v2(62.2,25.5) 62.2,25.46 63.58,24.08 63.58,22.67
  BOTTOM w0.127: J4.2 46.16,2.35 46.42,2.1 57.09,2.1 57.59,2.61 57.59,4.39 57.85,4.64 57.85,6.8 57.97,6.93 57.97,13.78 58.12,13.92 v1(58.24,13.92) ; 63.58,22.67 63.58,19.51 v1(64.47,18.62) 65.86,17.22 66.75,17.22 67.64,16.33 73.61,16.33 75.9,14.05 81.74,14.05 83.26,12.52 86.44,12.52 88.6,10.37 93.55,10.37 94.69,11.51 106.12,11.51 v1(106.5,11.13)
P4_7/FXIO_LCD_RST: length 107.8
  TOP w0.102: 58.86,23.07 60.25,23.07 U1.T4
  TOP w0.127: 58.86,23.07 58.75,23.07 58.36,22.67 57.21,22.67 v1(56.96,22.42)
  BOTTOM w0.127: J8.7 115.75,33.48 115.75,9.33 111.33,4.9 82.25,4.9 82,5.15 62.7,5.15 59.24,8.6 59.24,14.45 57.99,15.7 57.99,19.1 57.21,19.88 57.21,22.17 v1(56.96,22.42)
P4_12/ARD_A4: length 36.6
  TOP w0.102: 61.79,22.67 62.48,23.37 62.48,23.71 U1.T6
  TOP w0.127: R299.2 49.21,25.59 52.13,22.67 55.94,22.67 v1(56.2,22.42) 56.69,21.92 57.99,21.92 58.63,22.56 61.67,22.56 61.79,22.67
  BOTTOM w0.127: v1(56.2,22.42) 56.2,21.91 55.69,21.4 55.69,14.16 56.2,13.66 56.2,8.45 57.34,7.31 57.34,5.15 56.32,4.13 J4.10
P4_13: length 36.8
  TOP w0.102: 62.17,22.67 62.69,23.19 U1.T7
  TOP w0.127: R298.2 R57.1 50.48,23.94 52.01,22.42 55.56,22.42 56.07,21.91 56.2,21.91 v1(56.7,21.4) 56.97,21.67 58.12,21.67 58.63,22.18 61.67,22.18 62.17,22.67
  BOTTOM w0.127: J4.12 59.88,4.39 59.88,6.54 58.99,7.43 58.99,14.32 57.74,15.57 57.74,18.85 56.96,19.63 56.96,21.28 56.83,21.4 v1(56.7,21.4)
P4_13/TRIG_IN8-MC_ENC_B: length 35.9
  TOP w0.127: v1(44.77,19.37) 44.51,19.63 44.51,21.78 46.67,23.94 R57.2
  BOTTOM w0.127: v1(44.77,19.37) 44.13,20.01 38.42,20.01 37.02,18.61 36.13,18.61 30.8,13.28 30.8,12.51 28.38,10.1 26.22,10.1 23.3,7.18 J3.1
P4_14/FXIO_LCD_CS: length 83.7
  TOP w0.102: v2(62.72,25.97) 62.8,25.89 62.8,25.89 U1.N8
  TOP w0.127: J8.9 114.36,32.33 114.36,13.28 113.48,12.4 107.52,12.4 v1(106.95,11.83)
  BOTTOM w0.102: 63.83,22.67 63.83,24.85 62.72,25.97 v2(62.72,25.97)
  BOTTOM w0.127: v1(106.95,11.83) 106.88,11.76 94.57,11.76 93.42,10.62 88.72,10.62 86.57,12.78 83.52,12.78 81.99,14.3 76.02,14.3 73.74,16.59 67.77,16.59 66.88,17.48 66.5,17.48 63.83,20.14 63.83,22.67
P4_15: length 34.9
  TOP w0.102: U1.T8 62.89,23.7 62.89,23.01 62.55,22.67
  TOP w0.127: 62.55,22.67 61.04,21.16 57.48,21.16 57.22,20.9 56.32,20.9 R25.1 55.94,21.53 55.56,21.91 v1(55.31,21.91)
  BOTTOM w0.127: J4.4 49.97,4.64 54.16,4.64 54.93,5.4 54.93,8.32 53.66,9.59 53.66,17.21 55.31,18.86 v1(55.31,21.91)
P4_15/CAN1_RXD: length 1.8
  TOP w0.127: U11.4 54.2,21.49 54.42,21.28 R25.2
P4_16: length 59.6
  TOP w0.102: U1.R8 63.48,24.21 63.48,23.22 62.93,22.67
  TOP w0.127: 62.93,22.67 61.17,20.91 60.15,20.91 56.96,17.72 v1(56.2,17.72) R67.1 ; R92.1 37.27,16.06 37.53,16.32 40.19,16.32 40.58,15.94 40.58,15.05 40.19,14.67 40.19,9.72 41.08,8.83 43.37,8.83 44.89,7.31 44.89,4.64 45.15,4.39 50.23,4.39 J4.6
  BOTTOM w0.127: v1(56.2,17.72) 56.2,14.29 56.58,13.91 56.58,8.58 57.59,7.56 57.59,4.77 57.34,4.51 57.34,2.73 56.96,2.35 52.26,2.35 J4.6
P4_16/CAN1_TXD: length 2.4
  TOP w0.127: U11.1 53.74,19.54 54.8,18.48 R67.2
P4_17: length 102.6
  TOP w0.102: 63.31,22.67 63.69,23.05 U1.R9
  TOP w0.127: v1(58.5,18.62) 58.5,18.63 60.52,20.65 61.29,20.65 63.31,22.67 ; R169.2 100.92,7.32 v1(100.66,7.06) ; v1(60.9,7.7) 60.9,2.99 60.13,2.23 54.93,2.23 J4.8 52.51,2.1 45.02,2.1 44.64,2.48 44.64,7.18 43.24,8.58 40.96,8.58 39.94,9.59 39.94,14.42 39.69,14.67 R88.1
  BOTTOM w0.127: v1(58.5,18.62) 58.24,18.37 58.24,15.83 59.5,14.57 59.5,9.1 v1(60.9,7.7) 63.19,5.4 81.09,5.4 82.99,7.31 100.42,7.31 v1(100.66,7.06)
P4_18: length 78.3
  TOP w0.102: v2(63.71,25.86) 64.07,25.5 U1.N10
  TOP w0.127: v1(93.53,11.64) R167.2 ; v1(82.76,31.19) 82.76,32.97 79.06,36.67 J5.1
  BOTTOM w0.102: 67.01,22.67 67.01,23.32 65.86,24.46 65.48,24.46 64.09,25.86 v2(63.71,25.86)
  BOTTOM w0.127: 67.01,22.67 67.01,21.67 65.86,20.53 65.86,18.87 67.77,16.97 73.74,16.97 76.15,14.56 82.12,14.56 83.52,13.16 86.57,13.16 88.85,10.87 92.77,10.87 v1(93.53,11.64) 93.53,14.57 92.92,15.19 92.92,17.1 90.63,19.38 85.8,19.38 84.66,20.53 84.66,28.27 82.76,30.18 v1(82.76,31.19)
P4_19: length 101.2
  TOP w0.102: U1.R10 63.9,24.21 63.9,22.88 63.69,22.67
  TOP w0.127: v1(95.2,8.08) 94.69,8.08 93.79,8.99 R168.2 ; 63.69,22.67 59.77,18.75 v1(59.39,18.75)
  BOTTOM w0.127: v1(59.39,18.75) 59.51,18.62 59.51,17.86 58.88,17.22 58.88,15.95 60.02,14.81 60.02,9.73 63.84,5.91 80.83,5.91 82.74,7.81 94.94,7.81 v1(95.2,8.08) 97.87,8.08 98.13,7.81 113.47,7.81 115.25,9.59 115.25,28.9 J8.11
P4_20/FXIO_LCD_WR: length 104.5
  TOP w0.102: 64.08,22.67 64.48,23.08 64.48,23.71 U1.T10
  TOP w0.127: 64.08,22.67 59.51,18.11 v1(59.01,18.11)
  BOTTOM w0.127: v1(59.01,18.11) 58.5,17.6 58.5,15.95 59.75,14.7 59.75,9.59 63.69,5.66 80.96,5.66 82.87,7.56 113.6,7.56 115.5,9.46 115.5,30.68 113.47,32.71 111.44,32.71 J8.10
P4_21/TRIG_IN9-MC_ENC_A: length 50.1
  TOP w0.102: U1.T11 64.69,22.91 64.46,22.67
  TOP w0.127: v1(52.78,18.62) 53.9,18.62 55.42,17.1 57.99,17.1 58.5,17.6 59.39,17.6 64.46,22.67
  BOTTOM w0.127: J3.3 27.11,4.64 29.29,4.64 29.8,5.15 29.8,6.56 30.69,7.44 38.17,7.44 48.97,18.24 52.4,18.24 v1(52.78,18.62)
P4_22/FXIO_D30-CAMERA_PCLK: length 84.2
  TOP w0.102: 64.84,22.67 64.9,22.73 64.9,23.71 U1.T12
  TOP w0.127: 64.84,22.67 64.84,22.55 59.64,17.35 58.63,17.35 57.61,16.33 44.27,16.33 39.32,21.29 39.32,31.83 40.21,32.72 40.21,37.16 45.16,42.12 45.16,43 45.8,43.64 v1(45.8,45.54)
  BOTTOM w0.127: v1(45.8,45.54) 48.97,45.54 51.89,42.62 65.86,42.62 65.99,42.75 68.66,42.75 69.42,41.99 SJ4.3
P4_23/FXIO_LCD_TE: length 99.2
  TOP w0.102: 65.21,22.67 65.21,23.48 U1.U12
  TOP w0.127: 65.21,22.67 65.21,22.41 59.51,16.72 v1(59.39,16.72)
  BOTTOM w0.127: v1(59.39,16.72) 59.39,15.83 60.28,14.94 60.28,9.98 64.09,6.17 80.72,6.17 82.62,8.07 94.43,8.07 94.95,8.59 97.87,8.59 98.38,8.08 113.36,8.08 114.99,9.72 114.99,28.52 113.47,30.04 111.57,30.04 J8.12
P5-9V_VIN: length 27.2
  TOP w0.762: J19.1 27.36,13.02 26.73,12.39 C112.1 C110.1 C111.1 30.67,11.37 31.18,10.86 31.18,8.58 32.07,7.69 41.97,7.69 42.73,6.93 42.73,4 42.1,3.37 J3.16
P5_0/EXTAL32K: length 5.4
  TOP w0.127: U1.U16 67.19,20.7 67.37,20.51 C95.1 67.75,20.01 67.01,19.27 Y2.2
P5_1/XTAL32K: length 6.4
  TOP w0.127: Y2.1 69.51,19.27 68.64,20.13 C94.1 69.02,20.51 69.15,20.64 69.15,22.17 68.52,22.8 67.88,22.8 67.69,22.99 U1.U17
P5_2/MIKROE_RESET: length 23
  TOP w0.102: v2(64.19,26.49) U1.M10
  BOTTOM w0.102: v2(64.19,26.49) 64.85,26.49 64.98,26.62 68.02,26.62 68.28,26.37 68.52,26.37
  BOTTOM w0.127: J6.2 81.61,16.09 81.61,17.1 79.83,18.87 77.12,18.87 69.63,26.37 68.52,26.37
P5_3/ADC1_B11-MIKROE_AN: length 20.3
  TOP w0.102: v2(64.69,25.99) U1.N11
  BOTTOM w0.102: v2(64.69,25.99) 65.06,26.37 67.9,26.37 68.3,25.96 68.52,25.96
  BOTTOM w0.127: J6.1 79.06,17.88 78.31,18.62 77.02,18.62 69.67,25.96 68.52,25.96
P5_4/PMOD_RESET: length 47.6
  TOP w0.102: U1.M12 v2(65.19,25.48)
  TOP w0.127: v1(91.77,11.64) 92.28,11.13 92.28,8.84 94.57,6.56 94.57,4.88 J7.4
  BOTTOM w0.102: 67.39,22.67 67.39,23.32 66.37,24.34 66.37,25.1 65.99,25.48 v2(65.19,25.48)
  BOTTOM w0.127: v1(91.77,11.64) 91.26,11.13 89.11,11.13 86.82,13.41 83.77,13.41 82.37,14.81 76.28,14.81 73.74,17.35 67.77,17.35 66.25,18.87 66.25,20.53 67.39,21.67 67.39,22.67
P5_5/PMOD_INT: length 50.6
  TOP w0.102: U1.K12 65.19,27.41 65.09,27.51 v2(64.98,27.51)
  TOP w0.127: v1(89.23,11.64) 89.49,11.38 89.49,5.16 89.87,4.78 93.8,4.78 94.57,4.02 94.57,2.87 94.95,2.49 97.23,2.49 J7.2
  BOTTOM w0.102: 68.52,26.62 68.26,26.88 65.61,26.88 v2(64.98,27.51)
  BOTTOM w0.127: v1(89.23,11.64) 87.07,13.79 84.03,13.79 82.76,15.06 82.76,17.48 80.99,19.24 77.28,19.24 69.9,26.62 68.52,26.62
P5_6/MIKROE_INT: length 24.9
  TOP w0.102: v2(65.69,27.51) U1.K13
  TOP w0.127: J5.2 81.6,35.51 v1(81.87,35.24)
  BOTTOM w0.102: v2(65.69,27.51) 65.69,28.1 67.39,29.8 67.39,31.32 67.77,31.7 68.52,31.7
  BOTTOM w0.127: 68.52,31.7 69.17,31.7 71.71,34.24 73.99,34.24 74.99,35.24 v1(81.87,35.24)
P5_7: length 87.5
  TOP w0.102: v2(65.69,25.99) U1.L13
  TOP w0.127: v1(21.65,1.97) 21.14,2.48 21.14,14.67 20.89,14.93 17.09,14.93 16.96,15.05 R257.2 16.45,15.43 15.81,14.8 15.3,14.8 15.14,14.96 U41.6 ; v1(66.74,20.39) 66.12,20.39 64.98,19.24 64.98,18.37 62.69,16.08 62.05,16.08 59,13.03 v1(58.5,13.03)
  BOTTOM w0.102: 67.77,22.67 67.77,23.32 66.63,24.46 66.63,25.35 65.99,25.99 v2(65.69,25.99)
  BOTTOM w0.127: v1(21.65,1.97) 21.78,1.85 57.21,1.85 57.85,2.48 57.85,4.26 58.86,5.27 J4.11 58.23,6.54 58.23,12.76 v1(58.5,13.03) ; v1(66.74,20.39) 66.86,20.39 67.77,21.29 67.77,22.67
PIO0_5-ISP_EN-LED_SWD_ACT: length 17.8
  TOP w0.127: D7.C 27.46,38.14 28,38.68 JP5.2 R127.2 ; U8.A7 28.51,27.88 v2(28.76,28.13)
  BOTTOM w0.102: 28.76,31.82 v2(28.76,28.13)
  BOTTOM w0.127: JP5.2 29.53,37.27 28.51,36.26 28.51,32.2 28.76,31.94 28.76,31.82
SNS_LIGHT_ADC: length 28.5
  TOP w0.127: v1(61.67,39.45) 61.67,38.57 R38.1 ; Q2.2 37.79,44.78 C100.1 R178.1 v1(40.85,44.78)
  BOTTOM w0.127: v1(61.67,39.45) 61.17,39.96 56.85,39.96 56.47,40.34 54.05,40.34 53.16,41.23 50.62,41.23 47.58,44.27 43.89,44.27 43.39,43.77 41.86,43.77 v1(40.85,44.78)
USB1_CC1: length 11.6
  TOP w0.127: J11.A5 6.53,22.81 6.92,22.42 6.92,20.77 9.33,18.36 11.24,18.36 13.32,16.27 U41.1
USB1_CC2: length 13.5
  TOP w0.127: J11.B5 4.25,20.26 4,20.01 4,18.23 4.25,17.97 11.11,17.97 13.22,15.87 U41.2
USB1_ID: length 70.3
  TOP w0.102: U1.P11 v2(64.2,25)
  TOP w0.127: 9.84,21.9 10.21,21.9 10.35,22.04 v1(10.35,22.55) 10.6,22.8 R93.1 ; U41.9 15.14,17.34 15.27,17.47 v1(15.3,17.47) 15.18,17.59 R265.2 15.68,18.24 15.69,18.23 R295.1 16.57,18.61 16.83,18.86 17.97,18.86 19.75,17.09 40.7,17.09 42.35,15.43 59.88,15.43 64.46,20.02 v1(64.59,20.02)
  BOTTOM w0.102: 64.47,22.67 64.47,24.21 64.2,24.48 v2(64.2,25)
  BOTTOM w0.127: v1(15.3,17.47) 15.3,18.36 14.29,19.37 14.29,20.01 11.75,22.55 v1(10.35,22.55) ; 64.47,22.67 64.47,20.4 64.59,20.27 v1(64.59,20.02)
USB1_VBUS: length 39.2
  TOP w0.102: U1.U14 66.19,22.67
  TOP w0.127: v1(41.46,15.18) 60.01,15.18 63.95,19.13 64.47,19.13 66.48,21.14 66.48,22.19 66.19,22.49 66.19,22.67 ; v1(38.42,8.96) R91.1
  TOP w0.381: R91.1 R89.2
  BOTTOM w0.381: v1(41.46,15.18) 41.46,12.64 TP15.1 38.81,9.36 v1(38.42,8.96)
USB_OTG_VBUS: length 56
  TOP w0.254: U4.D1 36.75,11.39 36.89,11.24 37.15,11.5 U4.D2 U4.C2 ; U5.6 7.55,20.9 7.37,21.08 7.37,22.61 7.68,22.93
  TOP w0.381: C41.1 34.61,10.35 34.1,10.86 32.57,10.86 29.91,13.53 29.91,14.8 29.15,15.56 19.11,15.56 v1(18.99,15.43) ; v1(18.35,13.66) 17.46,12.77 R276.2
  TOP w0.508: C41.1 35.5,9.59 35.88,9.97 R89.1 36.64,10.61 36.89,10.86 36.89,11.24
  BOTTOM w0.381: v1(18.99,15.43) 19.11,15.31 19.11,14.04 18.73,13.66 v1(18.35,13.66) 18.1,13.66 16.19,15.56 13.68,15.56 TP16.1 9.86,19.38 6.08,19.38 J11.A9
  BOTTOM w0.508: J11.A4 J11.B9 4,23.66 3.49,23.15 3.49,20.01 4.09,19.41 J11.B4 J11.A9
VDIG: length 4.6
  TOP w0.102: U6.D12 98.43,30.61 97.73,29.91 97.73,28.77 97.66,28.71
  TOP w0.127: 97.66,28.71 97.47,28.52 97.47,27.88 96.96,27.37 C47.1
VREF_MCULINK: length 13.1
  TOP w0.254: U8.G2 U8.G1 25.21,31.31
  TOP w0.381: 25.21,31.31 25.08,31.44 v1(25.08,32.83) C70.1
  TOP w0.508: L12.2 27.96,33.6 C71.1 C70.1
  BOTTOM w0.381: v1(25.08,32.83) 26,33.76 26,35.37 25.73,35.64 25.73,37.92 25.1,38.56 TP21.1
N84836: length 1.8
  TOP w0.127: R116.2 R117.1 C69.1
N85250: length 1.4
  TOP w0.127: D6.A R118.2
N85474: length 1.4
  TOP w0.127: D7.A R119.2
N85648:
  vias: v1(20.51,26.36)
N85680: length 1.4
  TOP w0.127: D8.A R120.2
N85830:
  vias: v1(20.38,25.09)
N87448: length 6.7
  TOP w0.203: R121.2 R122.1 17.59,26.99 21.02,26.99 21.41,27.38 U8.N8
N301213: length 6.2
  TOP w0.127: J12.9 8.19,9.08 8.57,8.7 R150.1 R148.2 9.46,6.16 9.25,5.95 D10.C
N383974: length 2
  TOP w0.127: R168.1 95.55,9.34 95.95,8.94 D13.3
N384008: length 1.1
  TOP w0.127: D13.4 99.87,8.94 99.9,8.97
N384038: length 1.8
  TOP w0.127: R167.1 95.69,10.61 96.06,10.24 D13.2
N479793: length 1.1
  TOP w0.127: 99.9,10.24 98.78,10.24 D13.1
N629677: length 1.5
  TOP w0.127: R163.2 11.63,46.41 D12.A
N1489105: length 3.2
  TOP w0.254: R87.2 R88.2 38.29,14.29 v1(37.91,13.91) 37.15,13.15 U4.A2
N1489467: length 4.9
  TOP w0.254: Q1.3 34.99,15.43 v1(35.5,14.93) 35.71,14.71 R90.2 R92.2 37.27,14.7 37.27,14.04 36.75,13.51 U4.A1
N1489479: length 1.8
  TOP w0.254: R94.1 39.27,12.99 U4.A3
N1493095: length 4
  TOP w0.381: U11.3 54.22,20.84 54.67,20.39 C102.1 C103.1 R179.2
N1493367: length 2.5
  TOP w0.381: U11.8 49.47,19.54 49.3,19.37 R185.1 R181.2
N1493767: length 5.7
  TOP w0.508: J13.1 18.73,5.15 20.26,6.67 R182.1
N1493931: length 8.1
  TOP w0.381: v1(17.46,10.74) 18.02,10.18 R184.2 C105.1 ; R189.1 v1(13.98,10.18)
  BOTTOM w0.381: v1(17.46,10.74) 14.54,10.74 v1(13.98,10.18)
N1499275: length 33.9
  BOTTOM w0.127: SJ1.2 59.9,41.35 59.77,41.23 57.48,41.23 56.72,41.99 51.64,41.99 48.85,44.78 41.61,44.78 38.69,47.7 38.69,49.48 37.67,50.5 33.48,50.5 32.35,51.63 J2.6
N1499293: length 33
  BOTTOM w0.127: SJ2.2 54.94,38.43 54.82,38.31 53.55,38.31 52.53,39.32 50.12,39.32 47.45,41.99 41.48,41.99 40.85,42.62 37.67,42.62 33.1,47.2 33.1,49.61 32.46,50.24 30.79,50.24 J2.8
N1499583: length 22
  TOP w0.127: v1(52.15,31.07) 52.4,31.32 52.4,39.32 51.98,39.74 51.98,42.97 52.15,43.13 52.15,45.42 54.18,47.45 55.45,47.45 56.32,48.32 J1.3
  BOTTOM w0.127: SJ3.2 v1(52.15,31.07)
N14927971: length 1.4
  TOP w0.381: Q2.1 R172.1
N16628053: length 5
  TOP w0.635: U2.5 45.8,13.63 46.2,14.04 C3.1 46.93,14.29 C4.1 49.6,14.29 R8.1
N16629904: length 1.7
  TOP w0.508: R70.2 55.68,10.74 D3.A
N16780586: length 31
  TOP w0.508: R73.2 45.15,37.91 45.91,37.15 45.91,32.2 45.4,31.69 JP4.1
  POWER w0.508: JP4.1 45.53,31.69 50.5,26.72 50.5,25.99 52.53,23.95 56.34,23.95 57.74,22.56 57.74,21.16 58.24,20.65 v1(58.75,20.65)
  BOTTOM w0.508: v1(58.75,20.65) 59.64,20.65
N16872370: length 2.2
  TOP w0.102: 101.09,31.36 U6.A9
  TOP w0.127: C43.1 101.79,30.8 101.23,31.36 101.09,31.36
N16872454: length 2.2
  TOP w0.102: U6.B8 100.95,31.61 101.03,31.69 101.09,31.69
  TOP w0.127: 101.09,31.69 C48.1
N16872595: length 2.2
  TOP w0.102: U6.A1 100.14,33.54 100.14,34.42
  TOP w0.127: C51.1 100.14,34.99 100.14,34.42
N16872621: length 2.2
  TOP w0.102: U6.D2 98.49,33.57 98.49,34.42
  TOP w0.127: C52.1 98.49,34.42
N16872663: length 4.4
  TOP w0.102: U6.C3 98.84,32.87 98.23,33.47 98.23,33.85 97.98,34.1 97.98,34.42
  TOP w0.127: 97.98,34.42 97.98,35.9 98.22,36.14 C52.2
N16872673: length 4.3
  TOP w0.102: U6.C11 98.3,30.86 97.66,30.23
  TOP w0.127: R103.1 96.96,28.39 97.47,28.9 97.47,30.04 97.66,30.23
N16872680: length 2.1
  TOP w0.102: 99.28,34.42 U6.C1
  TOP w0.127: 99.28,34.42 99.28,35.15 C55.1
N16872761: length 11.7
  TOP w0.102: U6.A13 100.32,30.36 101.03,29.66 101.09,29.66
  TOP w0.127: 101.09,29.66 103.19,29.66 103.31,29.53 103.31,27.75 103.19,27.63 v1(103.19,27.12) 103.06,26.99 103.06,26.1 102.17,25.21 100.01,25.21 TP9.1
N16872798: length 2.1
  TOP w0.102: 101.09,32.06 100.89,32.06 100.69,31.87 U6.A7
  TOP w0.127: 101.09,32.06 101.27,32.06 C58.2
N16873720: length 4.6
  TOP w0.254: v1(65.72,13.4) R102.1 R101.2 ; L8.1 v1(67.75,13.4)
  BOTTOM w0.254: v1(67.75,13.4) v1(65.72,13.4)
N16874336: length 73.8
  TOP w0.254: L7.1 103.06,36.39 105.6,33.85 105.6,23.82 104.2,22.42 101.03,22.42 100.65,22.04 100.65,19.24 100.9,18.99 100.9,14.93 99.25,13.28 76.64,13.28 76.39,13.02 74.1,13.02 72.33,11.24 72.33,4.26 71.27,3.21 J14.4 J14.5
N16879603: length 4.6
  TOP w0.254: U7.3 96.54,19.71 95.69,18.86 95.19,18.86 94.3,19.75 R204.2
  TOP w0.508: R203.2 R204.2
N16880000: length 2.9
  TOP w0.254: L9.2 C59.1 R111.2 C56.1
N16880011: length 2.9
  TOP w0.254: L10.2 C60.1 R112.2 C57.1
N16886184: length 1.8
  TOP w0.102: U6.C17 99.28,28.45
  TOP w0.127: R96.2 99.28,27.6 99.28,28.45
N16886191: length 2.4
  TOP w0.102: U6.B16 99.62,28.45
  TOP w0.127: 99.62,28.45 99.62,28.27 R99.2
N16886584: length 4.2
  TOP w0.102: 97.73,34.42 97.73,33.98 97.98,33.72 97.98,33.34 98.71,32.61 U6.D4
  TOP w0.127: R106.2 97.73,35 97.73,34.42
N16886590: length 2.9
  TOP w0.102: 97.66,32.4 98.19,31.87 U6.C7
  TOP w0.127: R107.2 97.66,32.4
N16886596: length 3.1
  TOP w0.102: 97.66,32.9 98.44,32.12 U6.D6
  TOP w0.127: 97.66,32.9 97.47,33.09 97.47,33.47 R108.2
N16886605: length 4
  TOP w0.102: U6.C5 98.58,32.36 97.73,33.21 97.73,33.6 97.66,33.66
  TOP w0.127: 97.66,33.66 97.47,33.85 97.47,34.36 R109.2
N16887090: length 2.5
  TOP w0.102: 97.66,31.36 U6.C9
  TOP w0.127: R105.2 97.14,31.11 97.4,31.36 97.66,31.36
N16887102: length 2.2
  TOP w0.102: U6.D8 97.93,31.61 97.66,31.88
  TOP w0.127: R104.2 97.42,32.13 97.66,31.88
N16921653: length 3.2
  TOP w0.254: J14.3 69.21,13.08 69.79,13.66 L6.1
N16921845: length 2.6
  TOP w0.254: L9.1 80.55,11.24 J21.3
N16921915: length 13.3
  TOP w0.254: J21.5 J21.4 80.96,7.3 81.98,8.32 L10.1
N17029289: length 3.1
  TOP w0.127: R191.1 R202.2 90.48,31.06 U10.3
N17030310: length 3.5
  TOP w0.127: R176.2 R175.1 89.85,30.17 89.36,30.66 U10.2
N17030790: length 1.6
  TOP w0.127: U10.9 85.64,30.66 R197.2
N17362656: length 1.6
  TOP w0.127: U41.11 14.34,17.16 13.65,17.85 R278.2
N17362693: length 2.9
  TOP w0.203: R276.1 C150.1 14.34,14.49 U41.4
N17362702: length 1.7
  TOP w0.127: R210.1 15.99,15.87 U41.7
N17362725: length 1.9
  TOP w0.127: U41.8 15.63,16.27 16.57,17.21 R211.1
N17363203: length 2.9
  TOP w0.127: U41.5 14.74,14.85 15.3,14.29 R294.2
N17363355: length 2.8
  TOP w0.127: R297.2 12.25,15.31 v1(12.51,15.56) 12.76,15.56 13.27,15.05 13.78,15.05 13.94,15.22 U41.3
N17363759: length 15.8
  TOP w0.127: R295.2 18.1,18.23 19.62,16.7 31.18,16.7 v1(31.56,16.32) 31.8,16.09 Q1.2
N17508182: length 2.7
  TOP w0.508: R80.2 R81.1 77.02,20.64 R86.1
N17592677: length 11.5
  TOP w0.203: J10.A9 6.05,34.52 6.7,34.52 7.69,35.51 U9.6
  BOTTOM w0.508: J10.A4 J10.B9 4.7,38.77 3.97,38.77 3.61,38.41 3.61,35.12 4.21,34.52 4.7,34.52 J10.B4 J10.A9
N17592697: length 2.3
  TOP w0.127: J10.A5 6.06,37.91 R214.1
N17592749: length 7.2
  TOP w0.127: J10.B5 4.7,35.37 4.25,35.37 4,35.12 4,33.34 4.25,33.09 6.81,33.09 7.32,33.6 R213.1
N17598018: length 1.4
  TOP w0.203: v2(61.66,24.97) 61.66,24.97 U1.R4
  BOTTOM w0.381: v2(61.66,24.97) 61.66,24.97 R23.2
N17616471: length 7.2
  TOP w0.508: J6.7 92.63,17.73 91.26,17.73 90.76,18.24 C114.1 R206.2
N17616475: length 4.6
  TOP w0.508: C115.1 R207.2 94.31,38.95 J5.7
N1687256223: length 11.1
  TOP w0.102: 101.09,29.98 100.45,30.61 U6.B12
  TOP w0.127: TP8.1 101.92,24.45 103.57,26.1 v1(103.57,26.23) 103.69,26.36 103.69,29.51 103.29,29.91 101.15,29.91 101.09,29.98
N1687256228: length 10.1
  TOP w0.102: U6.A11 100.58,30.86 101.09,30.36
  TOP w0.127: 101.09,30.36 101.28,30.17 103.4,30.17 104.08,29.49 104.08,25.47 v1(103.82,25.21) TP5.1

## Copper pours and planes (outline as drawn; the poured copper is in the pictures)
GND on GND: 117.49,2 117.05,0.94 116,0.51 2,0.51 0.94,0.94 0.51,2 0.51,53.08 0.9,54.06 1.85,54.49 116,54.49 117.05,54.05 117.49,53
GND on POWER: 117.49,2 117.05,0.94 116,0.51 2,0.51 0.94,0.94 0.51,2 0.51,53.08 0.9,54.06 1.85,54.49 116,54.49 117.05,54.05 117.49,53 ; 10 cut-outs
P3V3_MCU on TOP: 42.73,34.61 42.73,28.39 42.48,28.13 40.83,28.13 40.58,27.88 40.58,23.56 41.08,23.05 42.23,23.05 42.35,22.93 42.35,22.42 42.1,22.17 40.7,22.17 39.69,23.18 39.69,31.44 40.58,32.33 40.58,37.02 41.85,38.29 42.35,38.29 42.61,38.04 42.61,34.74
P5V0 on TOP: 43.88,10.99 45.66,10.99 46.16,10.48 49.08,10.48 49.34,10.23 49.34,9.21 49.08,8.96 43.88,8.96 43.75,9.08 43.75,10.86
P5V0 on TOP: 11.62,37.79 11.75,37.91 14.92,37.91 15.18,37.66 15.18,34.48 15.05,34.36 15.05,29.4 14.41,28.77 9.21,28.77 9.08,28.9 9.08,30.42 9.46,30.8 11.37,30.8 11.62,31.06
P5V0 on BOTTOM: 14.41,28.64 13.14,28.64 12.76,28.26 12.76,26.23 13.27,25.72 14.16,25.72 18.6,21.28 18.6,18.86 20.89,16.58 20.89,13.4 20.76,13.28 19.87,13.28 19.75,13.4 19.75,15.69 14.79,20.64 14.79,22.04 11.37,25.47 11.37,30.42 12.13,31.18 14.29,31.18 14.54,30.93 14.54,28.77
P5V0 on POWER: 20.26,14.8 20.26,9.97 21.53,8.7 47.43,8.7 47.56,8.83 47.56,12.13 46.42,13.28 21.65,13.28 21.27,13.66 21.27,14.8 21.14,14.93 20.38,14.93
P5V_HDR_IN on TOP: 13.78,26.1 12.13,26.1 11.75,26.48 11.75,28.26 11.87,28.39 13.78,28.39 14.03,28.13 14.03,26.36
P5V_HDR_IN on BOTTOM: 13.27,28.13 13.14,28.01 13.14,26.48 13.52,26.1 14.41,26.1 19.11,21.4 19.11,19.24 21.4,16.96 21.4,13.78 21.65,13.53 23.3,13.53 23.68,13.91 23.68,19.24 17.08,25.85 17.08,27.63 16.57,28.13
P5V_MCU_LINK_USB on TOP: 13.14,38.17 11.62,38.17 11.11,38.68 9.33,38.68 9.21,38.8 9.21,39.82 9.33,39.95 13.14,39.95 13.27,39.82 13.27,38.29
P5V_USB_HS on TOP: 10.86,26.36 7.17,26.36 7.05,26.48 7.05,30.29 7.17,30.42 8.57,30.42 8.7,30.29 8.7,28.52 9.21,28.01 10.86,28.01 11.11,27.75 11.11,26.61
VDD_BOARD on TOP: 40.96,27.5 42.48,27.5 42.61,27.37 42.61,25.21 42.35,24.96 42.35,23.56 42.1,23.31 41.46,23.31 40.83,23.94 40.83,27.37
VDD_BOARD on TOP: 33.59,30.8 33.84,30.55 35.11,30.55 35.24,30.67 35.24,30.93 35.37,31.06 36.26,31.06 36.38,31.18 36.38,31.94 36.26,32.07 33.97,32.07 33.59,31.69
VDD_BOARD on POWER: 42.99,27.63 42.99,23.94 45.27,21.66 45.27,19.63 49.34,15.56 49.34,11.5 50.23,10.61 53.15,10.61 54.29,11.75 54.29,16.58 55.18,17.47 76.77,17.47 79.69,20.39 79.69,34.48 75.25,38.93 75.25,53.15 76.01,53.92 109.28,53.92 109.66,53.53 109.66,48.84 114.11,44.39 114.11,43.12 113.47,42.49 107.38,42.49 106.74,41.85 106.74,8.07 105.98,7.31 87.57,7.31 87.18,6.93 87.18,1.34 86.68,0.83 74.74,0.83 74.1,1.46 10.86,1.46 7.56,4.77 7.56,12.64 7.17,13.02 1.84,13.02 1.33,13.53 1.33,15.56 1.71,15.94 7.05,15.94 7.56,16.45 7.56,41.47 6.16,42.87 6.16,46.17 6.67,46.68 14.16,46.68 14.67,46.17 30.8,46.17 30.8,46.17 32.35,46.17 33.61,44.91 33.61,43.36 34.1,42.87 34.1,37.53 39.18,32.45 39.18,29.66 40.96,27.88 42.73,27.88
VDD_CORE on POWER: 64.2,27.5 66.61,27.5 67.63,28.52 71.06,28.52 71.31,28.26 71.31,26.36 70.93,25.98 64.2,25.98 63.94,26.23 63.94,27.25
VDD_MCU on TOP: 42.86,37.15 42.86,35.25 43.24,34.87 43.24,33.72 43.5,33.47 45.02,33.47 45.15,33.6 45.15,36.9 44.77,37.28 42.99,37.28
VDD_MCU on POWER: 63.56,29.4 63.56,28.01 63.44,27.88 61.28,27.88 58.99,30.17 57.34,30.17 57.09,29.91 57.09,29.28 57.47,28.9 58.48,28.9 60.9,26.48 62.8,26.48 63.82,25.47 71.56,25.47 72.33,24.71 74.48,24.71 75.25,23.94 75.25,18.23 74.87,17.85 61.78,17.85 61.15,18.48 61.15,23.05 60.7,23.5 58.8,23.5 57.47,24.83 57.47,25.85 57.09,26.23 55.56,26.23 55.31,25.98 52.89,25.98 52.77,26.1 52.77,27.63 49.21,31.18 48.32,31.18 46.16,33.34 43.5,33.34 42.99,33.85 42.99,37.66 43.37,38.04 74.74,38.04 78.55,34.23 78.55,26.36 78.29,26.1 74.87,26.1 72.33,28.64 72.33,30.67 71.69,31.31 65.47,31.31 ; 1 cut-out
VDD_P3 on POWER: 63.94,28.9 63.94,28.01 64.2,27.75 65.47,27.75 65.98,28.26 66.86,28.26 67.5,28.9 71.18,28.9 71.44,29.15 71.44,30.42 71.18,30.67 65.72,30.67
DCDC_LX on TOP: 67.63,25.21 68.39,25.21 68.64,24.96 71.56,24.96 71.69,24.83 71.69,22.93 71.56,22.8 70.17,22.8 68.26,24.71 67.63,24.71 67.5,24.83 67.5,25.09
